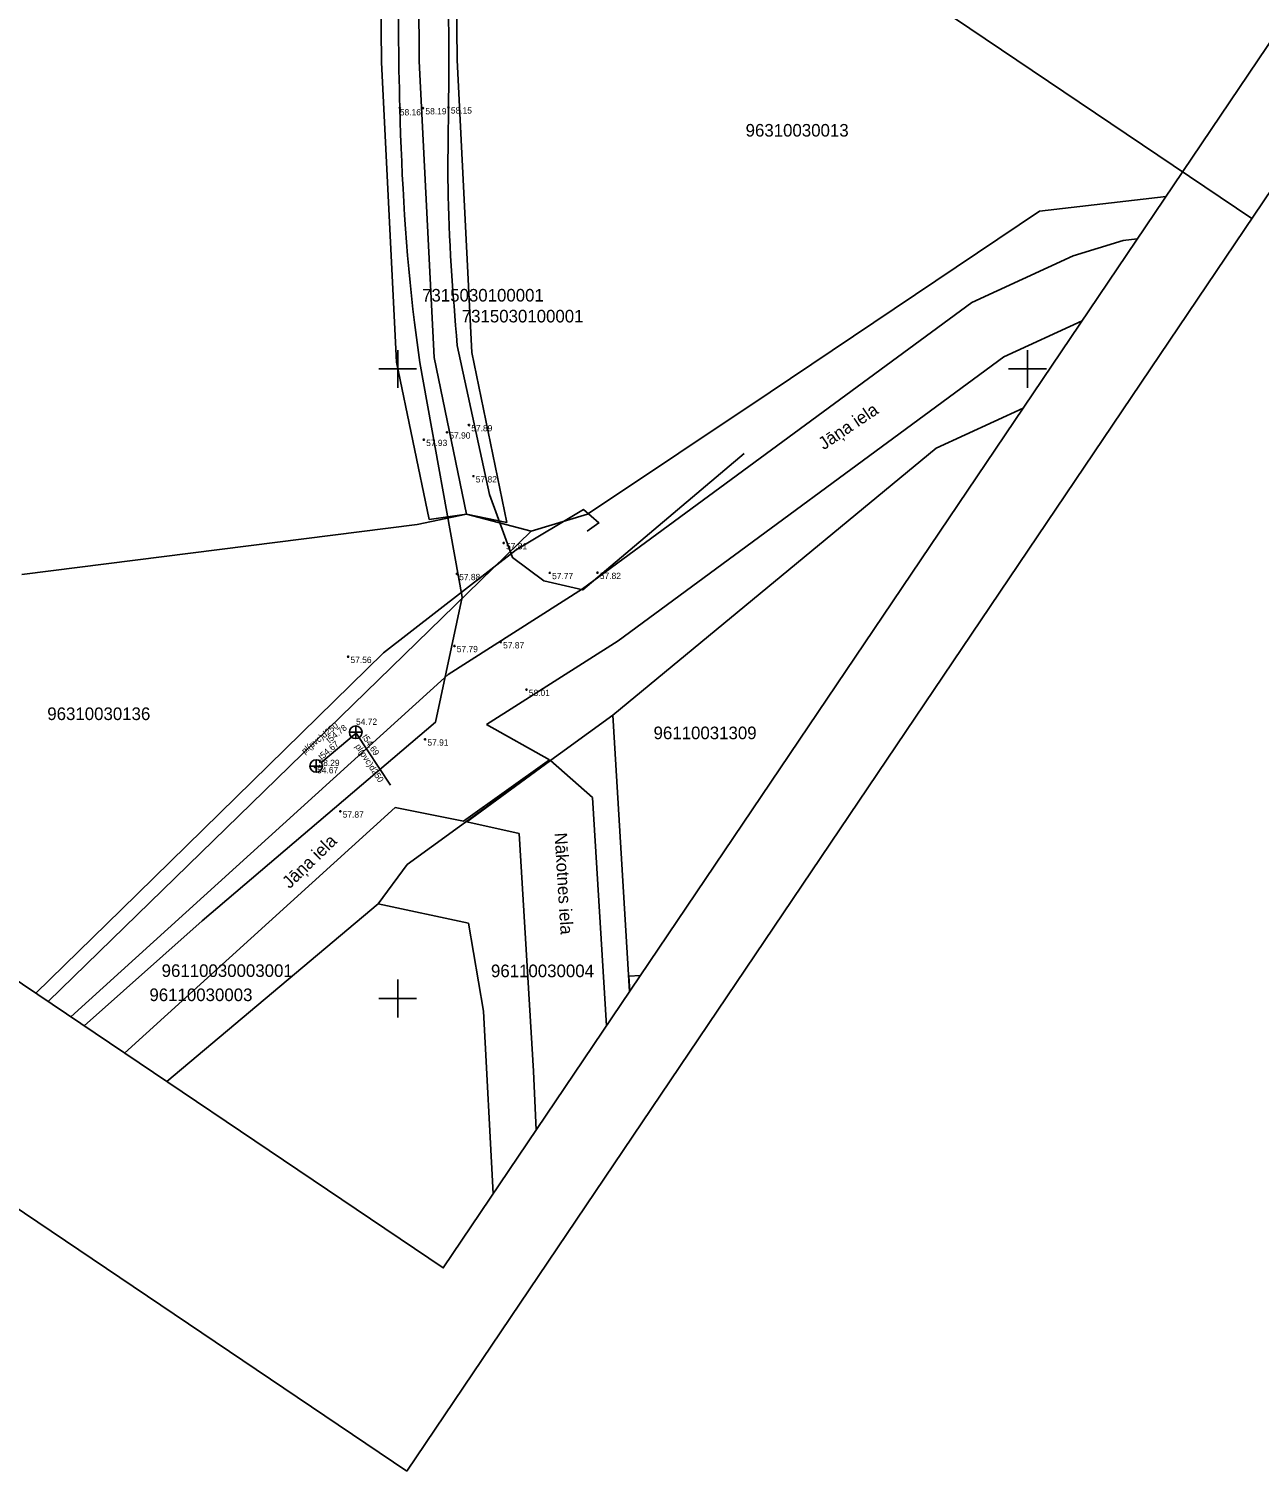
# Model space of a CAD drawing. Extents: x 562228 to 562468, y 414712 to 414970.
# Drawn here: x 562320.7 to 562418.4, y 414712.5 to 414827 of the extents above; entities that cross this region are included whole.
import ezdxf

# ---------------------------------------------------------------- set-up
doc = ezdxf.new("R2010")
doc.units = 0
for name, color, linetype in [('7315030100', 7, 'Continuous'), ('7315030100_TEXT', 7, 'Continuous'), ('BUVE_EKAS_UZMR_####_#', 7, 'Continuous'), ('BUVE_INZE_VEKT_####_#', 7, 'Continuous'), ('BUVE_INZE_VEKT_TKST_#', 7, 'Continuous'), ('CELI_CMAL_####_####_#', 7, 'Continuous'), ('CELI_IELA_####_TKST_#', 7, 'Continuous'), ('GEOD_ELEM_####_####_#', 7, 'Continuous'), ('RAMI_PLAN_####_TKST_#', 7, 'Continuous'), ('RELJ_AATZ_####_TKST_#', 7, 'Continuous'), ('RELJ_ELEM_####_####_#', 7, 'Continuous'), ('ROBZ_IERR_####_####_#', 7, 'Continuous'), ('ROBZ_IERR_####_TKST_#', 7, 'Continuous'), ('ROBZ_PROJ_####_####_#', 7, 'Continuous'), ('ROBZ_PROJ_####_TKST_#', 7, 'Continuous'), ('ROBZ_UZMR_####_####_#', 7, 'Continuous'), ('ROBZ_UZMR_####_TKST_#', 7, 'Continuous'), ('SAKT_VADP_KABE_####_#', 7, 'Continuous'), ('SKAN_ELEM_####_####_#', 7, 'Continuous'), ('SKAN_ELEM_PAST_TKST_#', 7, 'Continuous'), ('SKAN_VADP_PAST_####_I', 7, 'Continuous'), ('SKAN_VADP_PAST_TKST_I', 7, 'Continuous')]:
    doc.layers.add(name, color=color, linetype=linetype)

msp = doc.modelspace()

# ---------------------------------------------------------------- linework, layer by layer
at = {"layer": '7315030100'}
for p, q in [((562348.71, 414824.34), (562348.4, 414861.02)), ((562351.5, 414849.28), (562351.71, 414824.43)), ((562354.48, 414849.26), (562354.71, 414824.51)), ((562351.71, 414824.43), (562352.88, 414800.91)), ((562354.71, 414824.51), (562355.87, 414801.29)), ((562349.9, 414800.53), (562348.71, 414824.34)), ((562352.48, 414788.03), (562349.9, 414800.53)), ((562352.88, 414800.91), (562355.46, 414788.46)), ((562355.87, 414801.29), (562358.66, 414787.8)), ((562355.46, 414788.46), (562352.48, 414788.03)), ((562358.66, 414787.8), (562355.46, 414788.46))]:
    msp.add_line(p, q, dxfattribs=at)
at = {"layer": 'BUVE_EKAS_UZMR_####_#'}
msp.add_lwpolyline([(562368.42, 414750.56), (562368.34, 414751.77), (562369.27, 414751.82)], dxfattribs=at)
at = {"layer": 'BUVE_INZE_VEKT_####_#'}
for p, q in [((562403.62, 414808.99), (562407.61, 414810.2)), ((562407.61, 414810.2), (562408.72, 414810.32)), ((562395.58, 414805.28), (562403.62, 414808.99)), ((562364.66, 414782.54), (562395.58, 414805.28)), ((562404.33, 414803.81), (562398.13, 414800.95)), ((562398.13, 414800.95), (562367.49, 414778.41)), ((562354, 414775.73), (562364.66, 414782.54)), ((562367.49, 414778.41), (562357.05, 414771.75)), ((562324.04, 414748.54), (562354, 414775.73)), ((562357.05, 414771.75), (562362.05, 414768.94)), ((562362.05, 414768.94), (562355.21, 414764.08)), ((562355.48, 414764.03), (562362.14, 414768.89)), ((562362.14, 414768.89), (562365.47, 414765.97)), ((562349.8, 414765.17), (562328.31, 414745.66)), ((562355.21, 414764.08), (562349.8, 414765.17)), ((562365.47, 414765.97), (562366.58, 414747.83)), ((562359.64, 414763.11), (562355.48, 414764.03)), ((562360.78, 414744.23), (562359.64, 414763.11)), ((562360.99, 414739.54), (562360.78, 414744.23))]:
    msp.add_line(p, q, dxfattribs=at)
at = {"layer": 'CELI_CMAL_####_####_#'}
for points in [[(562377.5, 414793.28), (562364.69, 414782.45), (562361.61, 414783.16), (562359.1, 414785.01), (562357.28, 414790.02), (562354.72, 414801.85)], [(562351.74, 414800.51), (562355.11, 414781.86), (562352.99, 414771.94), (562334.47, 414756.16), (562325.1, 414747.82)]]:
    msp.add_lwpolyline(points, dxfattribs=at)
for points in [[(562351.74, 414800.51), (562351.33, 414803.68), (562350.16, 414820.75), (562350.12, 414844.64), (562350.09, 414866.54), (562349.8, 414884.43), (562348.86, 414903.65), (562348.78, 414921.02)], [(562354.72, 414801.85), (562353.99, 414814.52), (562354.03, 414820.78), (562353.75, 414844.81), (562353.48, 414866.3), (562353.37, 414884.8), (562352.79, 414903.63), (562352.89, 414909.6), (562354.13, 414911.73), (562356.64, 414912.73), (562368.11, 414912.72)]]:
    msp.add_spline(points, degree=3, dxfattribs=at)
at = {"layer": 'GEOD_ELEM_####_####_#'}
for p, q in [((562350, 414801.5), (562350, 414800)), ((562400, 414801.5), (562400, 414800)), ((562348.5, 414800), (562350, 414800)), ((562350, 414800), (562350, 414798.5)), ((562350, 414800), (562351.5, 414800)), ((562398.5, 414800), (562400, 414800)), ((562400, 414800), (562400, 414798.5)), ((562400, 414800), (562401.5, 414800)), ((562350, 414751.5), (562350, 414750)), ((562348.5, 414750), (562350, 414750)), ((562350, 414750), (562350, 414748.5)), ((562350, 414750), (562351.5, 414750))]:
    msp.add_line(p, q, dxfattribs=at)
at = {"layer": 'RAMI_PLAN_####_TKST_#'}
for p, q in [((562417.81, 414811.95), (562294.69, 414894.98)), ((562468.13, 414886.57), (562350.71, 414712.46)), ((562350.71, 414712.46), (562227.59, 414795.49))]:
    msp.add_line(p, q, dxfattribs=at)
msp.add_lwpolyline([(562458.44, 414884.06), (562347.98, 414958.55), (562243.14, 414803.09), (562353.61, 414728.6)], close=True, dxfattribs=at)
at = {"layer": 'RELJ_ELEM_####_####_#'}
for centre in [(562350.16, 414820.75), (562352.01, 414820.71), (562354.03, 414820.78), (562353.91, 414794.96), (562355.65, 414795.54), (562352.07, 414794.37), (562356.01, 414791.48), (562358.41, 414786.17), (562354.69, 414783.72), (562362.07, 414783.8), (562365.86, 414783.81), (562354.5, 414778), (562358.18, 414778.3), (562346.06, 414777.14), (562360.22, 414774.52), (562352.17, 414770.58), (562343.41, 414768.38), (562345.44, 414764.86)]:
    msp.add_circle(centre, 0.05, dxfattribs=at)
at = {"layer": 'ROBZ_IERR_####_####_#'}
for p, q in [((562411, 414813.7), (562400.96, 414812.53)), ((562400.96, 414812.53), (562379.57, 414798.14)), ((562379.57, 414798.14), (562365.06, 414788.46)), ((562360.58, 414787.11), (562355.46, 414788.46)), ((562365.06, 414788.46), (562360.58, 414787.11))]:
    msp.add_line(p, q, dxfattribs=at)
at = {"layer": 'ROBZ_PROJ_####_####_#'}
for p, q in [((562322.25, 414749.75), (562360.58, 414787.11)), ((562367.08, 414772.49), (562350.74, 414760.63)), ((562350.74, 414760.63), (562348.45, 414757.52))]:
    msp.add_line(p, q, dxfattribs=at)
at = {"layer": 'ROBZ_UZMR_####_####_#'}
for p, q in [((562351.5, 414849.28), (562351.71, 414824.43)), ((562351.71, 414824.43), (562352.88, 414800.91)), ((562352.88, 414800.91), (562355.46, 414788.46)), ((562392.75, 414793.7), (562399.66, 414796.89)), ((562367.08, 414772.49), (562392.75, 414793.7)), ((562355.46, 414788.46), (562351.54, 414787.65)), ((562351.54, 414787.65), (562320.15, 414783.67)), ((562368.41, 414750.56), (562367.08, 414772.49)), ((562331.66, 414743.4), (562348.45, 414757.52)), ((562348.45, 414757.52), (562355.62, 414755.98)), ((562355.62, 414755.98), (562356.82, 414749)), ((562356.82, 414749), (562357.57, 414734.48))]:
    msp.add_line(p, q, dxfattribs=at)
at = {"layer": 'SAKT_VADP_KABE_####_#'}
msp.add_lwpolyline([(562365.05, 414787.1), (562365.97, 414787.77), (562364.75, 414788.83), (562359.4, 414785.64), (562348.86, 414777.44), (562328.03, 414757.04), (562321.26, 414750.41)], dxfattribs=at)
at = {"layer": 'SKAN_ELEM_####_####_#'}
for p, q in [((562346.16, 414771.14), (562347.16, 414771.14)), ((562346.66, 414770.64), (562346.66, 414771.64)), ((562343.02, 414768.46), (562344.02, 414768.46)), ((562343.52, 414767.96), (562343.52, 414768.96))]:
    msp.add_line(p, q, dxfattribs=at)
for centre in [(562346.66, 414771.14), (562343.52, 414768.46)]:
    msp.add_circle(centre, 0.5, dxfattribs=at)
at = {"layer": 'SKAN_VADP_PAST_####_I'}
for p, q in [((562346.69, 414771.08), (562343.89, 414768.7)), ((562349.41, 414766.94), (562346.69, 414771.08))]:
    msp.add_line(p, q, dxfattribs=at)

# ---------------------------------------------------------------- texts
at = {"layer": '7315030100_TEXT'}
for p in [(562351.93, 414805.35), (562355.08, 414803.69)]:
    msp.add_text('7315030100001', height=1, dxfattribs=at).set_placement(p)
at = {"layer": 'BUVE_INZE_VEKT_TKST_#'}
msp.add_text('96110030003001', height=1, dxfattribs=at).set_placement((562331.25, 414751.71))
at = {"layer": 'CELI_IELA_####_TKST_#'}
for s, rotation, p in [('Jāņa iela', 33.936, (562383.82, 414793.53)), ('Jāņa iela', 44.2612, (562341.41, 414758.67)), ('Nākotnes iela', 273.479, (562362.44, 414763.14))]:
    msp.add_text(s, height=1, rotation=rotation, dxfattribs=at).set_placement(p)
at = {"layer": 'RELJ_AATZ_####_TKST_#'}
for s, p in [(' 58.16', (562349.98, 414820.13)), (' 58.19', (562352.01, 414820.21)), (' 58.15', (562354.03, 414820.28)), (' 57.90', (562353.91, 414794.46)), (' 57.89', (562355.65, 414795.04)), (' 57.93', (562352.07, 414793.87)), (' 57.82', (562356.01, 414790.98)), (' 57.81', (562358.41, 414785.67)), (' 57.88', (562354.69, 414783.22)), (' 57.77', (562362.07, 414783.3)), (' 57.82', (562365.86, 414783.31)), (' 57.79', (562354.5, 414777.5)), (' 57.87', (562358.18, 414777.8)), (' 57.56', (562346.06, 414776.64)), (' 58.01', (562360.22, 414774.02)), (' 57.91', (562352.17, 414770.08)), (' 54.67', (562343.41, 414767.88)), (' 57.87', (562345.44, 414764.36))]:
    msp.add_text(s, height=0.5, dxfattribs=at).set_placement(p)
at = {"layer": 'ROBZ_IERR_####_TKST_#'}
msp.add_text('96310030013', height=1, dxfattribs=at).set_placement((562377.62, 414818.45))
at = {"layer": 'ROBZ_PROJ_####_TKST_#'}
for s, p in [('96310030136', (562322.17, 414772.11)), ('96110030004', (562357.4, 414751.69)), ('96110030003', (562330.28, 414749.79))]:
    msp.add_text(s, height=1, dxfattribs=at).set_placement(p)
at = {"layer": 'ROBZ_UZMR_####_TKST_#'}
msp.add_text('96110031309', height=1, dxfattribs=at).set_placement((562370.31, 414770.59))
at = {"layer": 'SKAN_ELEM_PAST_TKST_#'}
for s, p in [(' 54.72', (562346.5, 414771.73)), (' 58.29', (562343.52, 414768.46))]:
    msp.add_text(s, height=0.5, dxfattribs=at).set_placement(p)
at = {"layer": 'SKAN_VADP_PAST_TKST_I'}
for s, rotation, p in [('pl(pvc)d250', 38.9711, (562342.6, 414769.39)), ('t54.78', 38.647, (562344.56, 414770.25)), ('t54.69', 303.2349, (562347.14, 414770.78)), ('t54.67', 40.3364, (562343.95, 414768.92)), ('pl(pvc)d250', 303.2982, (562346.59, 414770.02))]:
    msp.add_text(s, height=0.5, rotation=rotation, dxfattribs=at).set_placement(p)

doc.saveas('drawing.dxf')
